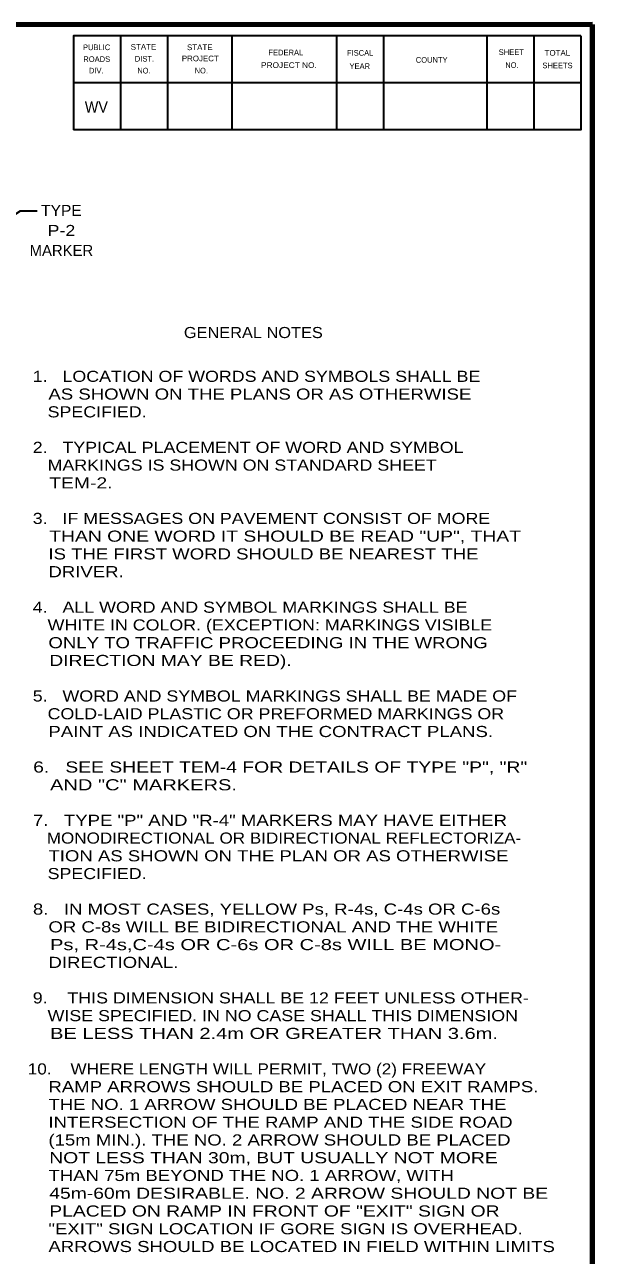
# Model space of a CAD drawing. Extents: x -96 to 617, y -65 to 388.
# Drawn here: x 484.1 to 611.9, y 105.8 to 383 of the extents above; entities that cross this region are included whole.
import ezdxf
from ezdxf.enums import TextEntityAlignment as Align

# ---------------------------------------------------------------- set-up
doc = ezdxf.new("R2010")
doc.units = 0
doc.layers.add('1', color=7, linetype='Continuous', lineweight=53)
doc.layers.add('61', color=7, linetype='Continuous', lineweight=35)

msp = doc.modelspace()

# ---------------------------------------------------------------- linework, layer by layer
at = {"layer": '1', "lineweight": 158}
msp.add_line((611.853, -55.407), (611.853, 383.009), dxfattribs=at)
at = {"layer": '1', "lineweight": 13}
msp.add_line((611.853, -55.407), (611.853, 383.009), dxfattribs=at)
at = {"layer": '1', "lineweight": 158}
msp.add_lwpolyline([(611.853, 383.009), (-47.897, 382.926), (-47.814, -55.407)], dxfattribs=at)
at = {"layer": '1', "lineweight": 35}
msp.add_lwpolyline([(476.015, 336.413), (483.098, 341.057), (486.879, 341.057)], dxfattribs=at)
at = {"layer": '61'}
for p, q in [((505.603, 380.509), (505.603, 359.343)), ((516.186, 380.509), (516.186, 359.343)), ((530.686, 380.509), (530.686, 359.343)), ((554.269, 380.509), (554.269, 359.343)), ((564.853, 380.509), (564.853, 359.343)), ((588.103, 380.509), (588.103, 359.343)), ((598.686, 380.509), (598.686, 359.343)), ((609.269, 369.926), (495.019, 369.926))]:
    msp.add_line(p, q, dxfattribs=at)
for points in [[(609.269, 380.509), (495.019, 380.509), (495.019, 359.343)], [(609.269, 380.509), (609.269, 359.343), (495.019, 359.343)]]:
    msp.add_lwpolyline(points, dxfattribs=at)

# ---------------------------------------------------------------- texts
at = {"layer": '1'}
for s, height, width, p in [('WV', 2.54, 0.95, (497.603, 363.176)), (' 1.   LOCATION OF WORDS AND SYMBOLS SHALL BE', 2.5, 1.2, (484.767, 302.543)), ('    AS SHOWN ON THE PLANS OR AS OTHERWISE', 2.5, 1.25, (484.767, 298.543)), ('    SPECIFIED.', 2.5, 1.2, (484.767, 294.543)), (' 2.   TYPICAL PLACEMENT OF WORD AND SYMBOL', 2.5, 1.2, (484.767, 286.543)), ('    MARKINGS IS SHOWN ON STANDARD SHEET', 2.5, 1.2, (484.767, 282.543)), ('    TEM-2.', 2.5, 1.3, (484.767, 278.543)), (' 3.   IF MESSAGES ON PAVEMENT CONSIST OF MORE', 2.5, 1.2, (484.767, 270.543)), ('    THAN ONE WORD IT SHOULD BE READ "UP", THAT', 2.5, 1.3, (484.767, 266.543)), ('    IS THE FIRST WORD SHOULD BE NEAREST THE', 2.5, 1.25, (484.767, 262.543)), ('    DRIVER.', 2.5, 1.25, (484.767, 258.543)), (' 4.   ALL WORD AND SYMBOL MARKINGS SHALL BE', 2.5, 1.2, (484.767, 250.543)), ('    WHITE IN COLOR. (EXCEPTION: MARKINGS VISIBLE', 2.5, 1.2, (484.767, 246.543)), ('    ONLY TO TRAFFIC PROCEEDING IN THE WRONG', 2.5, 1.25, (484.767, 242.543)), ('    DIRECTION MAY BE RED).', 2.5, 1.3, (484.767, 238.543)), (' 5.   WORD AND SYMBOL MARKINGS SHALL BE MADE OF', 2.5, 1.2, (484.767, 230.543)), ('    COLD-LAID PLASTIC OR PREFORMED MARKINGS OR', 2.5, 1.2, (484.767, 226.543)), ('    PAINT AS INDICATED ON THE CONTRACT PLANS.', 2.5, 1.25, (484.767, 222.543)), (' 6.   SEE SHEET TEM-4 FOR DETAILS OF TYPE "P", "R"', 2.5, 1.3, (484.767, 214.543)), ('    AND "C" MARKERS.', 2.5, 1.35, (484.767, 210.543)), (' 7.   TYPE "P" AND "R-4" MARKERS MAY HAVE EITHER', 2.5, 1.25, (484.767, 202.543)), ('    MONODIRECTIONAL OR BIDIRECTIONAL REFLECTORIZA-', 2.5, 1.15, (484.767, 198.543)), ('    TION AS SHOWN ON THE PLAN OR AS OTHERWISE', 2.5, 1.25, (484.767, 194.543)), ('    SPECIFIED.', 2.5, 1.2, (484.767, 190.543)), (' 8.   IN MOST CASES, YELLOW Ps, R-4s, C-4s OR C-6s', 2.5, 1.25, (484.767, 182.543)), ('    OR C-8s WILL BE BIDIRECTIONAL AND THE WHITE', 2.5, 1.25, (484.767, 178.543)), ('    Ps, R-4s,C-4s OR C-6s OR C-8s WILL BE MONO-', 2.5, 1.35, (484.767, 174.543)), ('    DIRECTIONAL.', 2.5, 1.25, (484.767, 170.543)), (' 9.    THIS DIMENSION SHALL BE 12 FEET UNLESS OTHER-', 2.5, 1.2, (484.767, 162.543)), ('    WISE SPECIFIED. IN NO CASE SHALL THIS DIMENSION', 2.5, 1.2, (484.767, 158.543)), ('    BE LESS THAN 2.4m OR GREATER THAN 3.6m.', 2.5, 1.35, (484.767, 154.543)), ('10.    WHERE LENGTH WILL PERMIT, TWO (2) FREEWAY', 2.5, 1.15, (484.767, 146.543)), ('    RAMP ARROWS SHOULD BE PLACED ON EXIT RAMPS.', 2.5, 1.25, (484.767, 142.543)), ('    THE NO. 1 ARROW SHOULD BE PLACED NEAR THE', 2.5, 1.25, (484.767, 138.543)), ('    INTERSECTION OF THE RAMP AND THE SIDE ROAD', 2.5, 1.25, (484.767, 134.543)), ('    (15m MIN.). THE NO. 2 ARROW SHOULD BE PLACED', 2.5, 1.25, (484.767, 130.543)), ('    NOT LESS THAN 30m, BUT USUALLY NOT MORE', 2.5, 1.3, (484.767, 126.543)), ('    THAN 75m BEYOND THE NO. 1 ARROW, WITH', 2.5, 1.25, (484.767, 122.543)), ('    45m-60m DESIRABLE. NO. 2 ARROW SHOULD NOT BE', 2.5, 1.3, (484.767, 118.543)), ('    PLACED ON RAMP IN FRONT OF "EXIT" SIGN OR', 2.5, 1.3, (484.767, 114.543)), ('    "EXIT" SIGN LOCATION IF GORE SIGN IS OVERHEAD.', 2.5, 1.25, (484.767, 110.543)), ('    ARROWS SHOULD BE LOCATED IN FIELD WITHIN LIMITS', 2.5, 1.25, (484.767, 106.543))]:
    msp.add_text(s, height=height, dxfattribs=dict(at, width=width)).set_placement(p)
for s, width, p in [('TYPE', 1.05, (492.339, 339.895)), ('P-2', 1.2, (492.339, 335.395)), ('GENERAL NOTES', 1.1, (535.538, 312.407))]:
    msp.add_text(s, height=2.5, dxfattribs=dict(at, width=width)).set_placement(p, align=Align.CENTER)
msp.add_text('MARKER', height=2.5, dxfattribs=at).set_placement((492.339, 330.895), align=Align.CENTER)
at = {"layer": '61'}
for s, height, rotation, p in [('PUBLIC', 1.271, 0.033, (497.186, 377.259)), ('FEDERAL', 1.27, 0.007, (538.936, 376.093)), ('FISCAL', 1.271, 359.942, (556.603, 376.009)), ('SHEET', 1.271, 0.059, (590.769, 376.176)), ('ROADS', 1.27, 0.124, (497.269, 374.593)), ('DIST.', 1.27, 0.056, (508.853, 374.676)), ('YEAR', 1.27, 0.105, (557.186, 373.009)), ('COUNTY', 1.269, 0.069, (572.103, 374.426)), ('SHEETS', 1.269, 359.959, (600.603, 373.176)), ('DIV.', 1.27, 359.932, (498.519, 372.009))]:
    msp.add_text(s, height=height, rotation=rotation, dxfattribs=at).set_placement(p)
for s, height, rotation, width, p in [('STATE', 1.271, 0.059, 1.05, (507.936, 377.343)), ('STATE', 1.271, 0.059, 1.05, (520.603, 377.259)), ('TOTAL', 1.27, 359.926, 1.05, (601.103, 376.009)), ('PROJECT', 1.27, 359.908, 1.05, (519.436, 374.759)), ('PROJECT NO.', 1.27, 359.922, 1.1, (537.269, 373.259)), ('NO.', 1.27, 359.852, 0.9, (592.269, 373.259)), ('NO.', 1.27, 359.852, 0.9, (509.436, 372.009)), ('NO.', 1.271, 0.225, 0.9, (522.353, 372.009))]:
    msp.add_text(s, height=height, rotation=rotation, dxfattribs=dict(at, width=width)).set_placement(p)

doc.saveas('drawing.dxf')
